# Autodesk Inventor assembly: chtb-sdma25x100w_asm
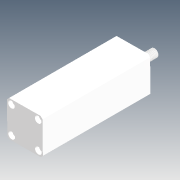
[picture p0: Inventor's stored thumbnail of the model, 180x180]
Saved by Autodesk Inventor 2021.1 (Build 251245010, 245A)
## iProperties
Company: Microsoft
Created: 2018-05
Part Number: chtb-sdma25x100w_asm
Description: STEP AP214
Document SubType Name: Assembly
Designer: user
Title: chtb-sdma25x100w_asm.STEP
Author: Windows
Revision Number: ÈÎºÎ
Sending System: SolidWorks 2015
Preprocessor: SwSTEP 2.0
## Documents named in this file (4)
- D:\Vault_2016\Projekty\Clamptek\Hydraulic\CHTB\CHTB-25\Inventor\chtb-sdma25x100w\chtb-sdma25x100w_asm.iam
- D:\Vault_2016\Projekty\Clamptek\Hydraulic\CHTB\CHTB-25\Inventor\chtb-sdma25x100w\CHTB-25QG.ipt
- D:\Vault_2016\Projekty\Clamptek\Hydraulic\CHTB\CHTB-25\Inventor\chtb-sdma25x100w\CHTB-SDMA25X100NBT.ipt
- D:\Vault_2016\Projekty\Clamptek\Hydraulic\CHTB\CHTB-25\Inventor\chtb-sdma25x100w\CHTB-SDMA25X100WHSG.ipt
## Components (3 placed, 3 different names)
1. CHTB-25QG_1
2. CHTB-SDMA25X100NBT_2
3. CHTB-SDMA25X100WHSG_3
